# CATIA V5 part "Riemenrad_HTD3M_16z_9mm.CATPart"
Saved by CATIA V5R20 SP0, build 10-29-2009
Part number: Riemenrad_HTD3M_16z_9mm
Bounding box of the stored display mesh (mm): x -10 to 10, y -9.999 to 9.999, z 0 to 24
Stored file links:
  C:\Users\Andi\Desktop\Plasma\Riemenrad_HTD3M_16z_9mm.CATPart
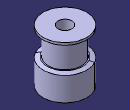
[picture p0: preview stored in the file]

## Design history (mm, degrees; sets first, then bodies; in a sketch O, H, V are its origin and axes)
AxisSystem1: origin (0, 0, 0), X (1, 0, 0), Y (0, 1, 0), Z (0, 0, 1)
Body1 (main body)
  Sketch1 on YZ plane of AxisSystem1, origin (0, 0, 0), H (0, 1, 0), V (0, 0, 1)
    point P1 (3.175, 0)
    line L1 (3.175, 0) -> (3.175, 24)
    line L2 (3.175, 24) -> (10, 24)
    line L3 (10, 24) -> (10, 23.0067)
    line L4 (10, 23.0067) -> (8.1089, 22.5)
    point P5 (8.1089, 22.5)
    line L5 (8.1089, 22.5) -> (7.6, 22.5)
    line L6 (7.6, 22.5) -> (7.6, 11.5)
    line L7 (7.6, 11.5) -> (8.1089, 11.5)
    point P8 (8.1089, 11.5)
    line L8 (8.1089, 11.5) -> (10, 10.9933)
    point P9 (10, 10.9933)
    line L9 (10, 10.9933) -> (10, 0)
    point P10 (10, 0)
    line L10 (10, 0) -> (3.175, 0)
    distance L1 V = 3.175
    distance L9 V = 10
    distance L10 L2 = 24
    distance L5 L7 = 11
    distance L7 L10 = 11.5
    angle L5 L4 = 15
    angle L7 L8 = 15 {= Sketch1.angle(L5 L4)}
    distance V P5 = 8.1089
    distance P8 V = 8.1089 {= Sketch1.distance(V P5)}
    distance V L6 = 7.6
    coincidence: P1 H, P9 L3, P10 H
    vertical: L1 V, L3 V, L6 V, L9 V
    horizontal: L2 H, L5 H, L7 H, L10 H
  Shaft1: profile Sketch1, axis edge [ZX plane of AxisSystem1 | YZ plane of AxisSystem1], angle 360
